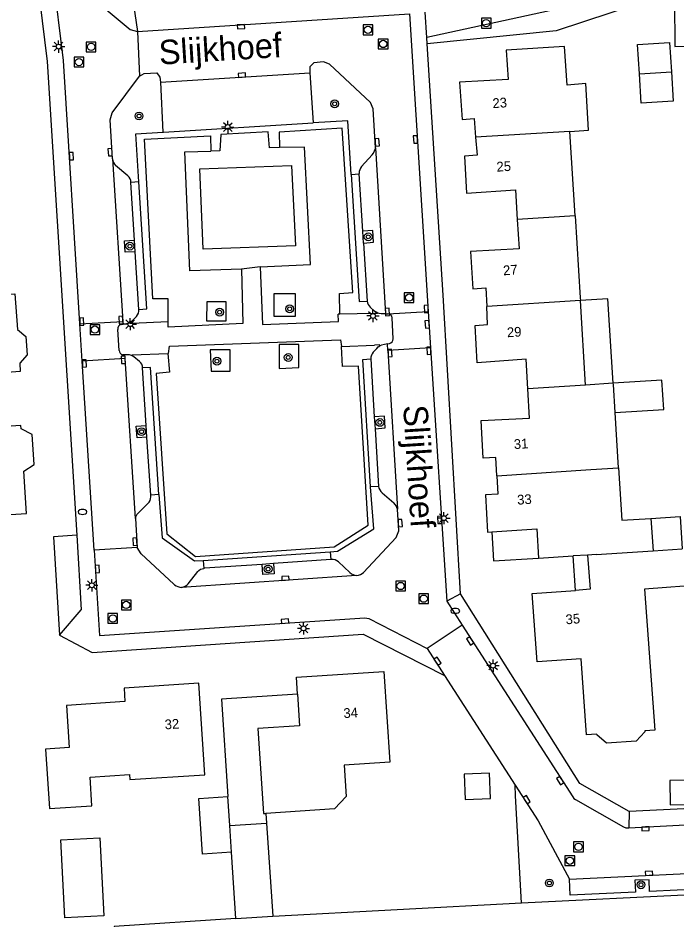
# Model space of a CAD drawing. Extents: x 140000 to 143000, y 403500 to 406000.
# Drawn here: x 140652.7 to 140720.3, y 403899.8 to 403992.2 of the extents above; entities that cross this region are included whole.
import ezdxf

# ---------------------------------------------------------------- set-up
doc = ezdxf.new("R2010")
doc.units = 0
for name, color, linetype in [('gg-afsc-erfafscheiding', 7, 'Continuous'), ('gg-afsc-hekwerk', 7, 'Continuous'), ('gg-anno-huisnummerreeks BGT', 7, 'Continuous'), ('gg-anno-openbare ruimte label', 7, 'Continuous'), ('gg-bbg-bassin', 7, 'Continuous'), ('gg-bbg-bijgebouw', 7, 'Continuous'), ('gg-bbg-gedigitaliseerde bebouwing', 7, 'Continuous'), ('gg-bbg-gedigitaliseerde bijgebouw', 7, 'Continuous'), ('gg-bbg-hoofdgebouw', 7, 'Continuous'), ('gg-bbg-luifel en loopbrug', 7, 'Continuous'), ('gg-bbg-overig bouwwerk', 7, 'Continuous'), ('gg-bbg-tussenscheiding', 7, 'Continuous'), ('gg-knt-bronhoudergrens', 7, 'Continuous'), ('gg-knt-verharding', 7, 'Continuous'), ('gg-knt-verharding nz', 7, 'Continuous'), ('gt-grn-groengrens', 7, 'Continuous'), ('gt-grn-weggrens', 7, 'Continuous'), ('gt-symb-boom', 7, 'Continuous'), ('gt-symb-brandkraan', 7, 'Continuous'), ('gt-symb-kolk', 7, 'Continuous'), ('gt-symb-lichtmast', 7, 'Continuous'), ('gt-symb-rioolschacht', 7, 'Continuous')]:
    doc.layers.add(name, color=color, linetype=linetype)

# ---------------------------------------------------------------- blocks, each defined once
blk = doc.blocks.new('gt0-BOOM')
at = {"layer": 'gt-symb-boom'}
for radius in [0.4, 0.2]:
    blk.add_circle((0, 0), radius, dxfattribs=at)
blk = doc.blocks.new('gt0-LMAST')
at = {"layer": 'gt-symb-lichtmast'}
for p, q in [((-0.182, 0.173), (-0.447, 0.438)), ((-0.005, 0.246), (-0.005, 0.621)), ((0.172, 0.173), (0.437, 0.438)), ((-0.255, -0.004), (-0.63, -0.004)), ((-0.182, -0.181), (-0.447, -0.446)), ((-0.005, -0.254), (-0.005, -0.629)), ((0.437, -0.446), (0.172, -0.181)), ((0.245, -0.004), (0.62, -0.004))]:
    blk.add_line(p, q, dxfattribs=at)
blk.add_circle((-0.005, -0.004), 0.25, dxfattribs=at)
blk = doc.blocks.new('gt0-KOLK')
at = {"layer": 'gt-symb-kolk'}
blk.add_lwpolyline([(0, 0), (0.375, 0), (0.375, 0.4), (-0.375, 0.4), (-0.375, 0), (0, 0)], dxfattribs=at)
blk = doc.blocks.new('gt0-RS')
at = {"layer": 'gt-symb-rioolschacht'}
blk.add_lwpolyline([(-0.5, -0.5), (0.5, -0.5), (0.5, 0.5), (-0.5, 0.5)], close=True, dxfattribs=at)
blk.add_circle((0, 0), 0.375, dxfattribs=at)
blk = doc.blocks.new('gt0-BR')
at = {"layer": 'gt-symb-brandkraan'}
for centre, radius, start, end in [((-0.244, 0), 0.206, 107.56694, 252.43307), ((0.599, -2.664), 3, 106.89205, 107.56694), ((0, -0.691), 0.938, 73.10799, 106.89205), ((-0.599, -2.664), 3, 72.43309, 73.10799), ((0.244, 0), 0.206, 287.56695, 72.43309), ((0.599, 2.664), 3, 252.43307, 253.10797), ((0, 0.691), 0.938, 253.10797, 286.89206), ((-0.599, 2.664), 3, 286.89206, 287.56695)]:
    blk.add_arc(centre, radius, start, end, dxfattribs=at)

msp = doc.modelspace()

# ---------------------------------------------------------------- linework, layer by layer
at = {"layer": 'gg-afsc-erfafscheiding'}
msp.add_lwpolyline([(140720.042, 403993.941), (140720.089, 403989.294), (140722.989, 403989.327)], dxfattribs=at)
at = {"layer": 'gg-afsc-hekwerk'}
msp.add_line((140704.351, 403901.52), (140759.387, 403904.142), dxfattribs=at)
at = {"layer": 'gg-bbg-bassin'}
msp.add_lwpolyline([(140661.095, 403908.172), (140661.513, 403900.183), (140657.519, 403899.973), (140657.101, 403907.962), (140661.095, 403908.172)], dxfattribs=at)
at = {"layer": 'gg-bbg-bijgebouw'}
for p, q in [((140674.425, 403909.422), (140678.194, 403909.672)), ((140674.605, 403906.711), (140674.425, 403909.422)), ((140678.194, 403909.672), (140678.828, 403900.136)), ((140675.058, 403899.886), (140674.605, 403906.711)), ((140675.058, 403899.886), (140678.828, 403900.136))]:
    msp.add_line(p, q, dxfattribs=at)
at = {"layer": 'gg-bbg-gedigitaliseerde bebouwing'}
for p, q in [((140717.637, 403940.917), (140717.843, 403937.605)), ((140717.843, 403937.605), (140720.836, 403937.797))]:
    msp.add_line(p, q, dxfattribs=at)
msp.add_lwpolyline([(140714.307, 403946.12), (140714.642, 403940.73), (140717.637, 403940.917)], dxfattribs=at)
at = {"layer": 'gg-bbg-gedigitaliseerde bijgebouw'}
msp.add_line((140716.445, 403986.508), (140719.738, 403986.713), dxfattribs=at)
msp.add_lwpolyline([(140719.738, 403986.713), (140719.925, 403983.719), (140716.631, 403983.513), (140716.445, 403986.508)], dxfattribs=at)
at = {"layer": 'gg-bbg-hoofdgebouw'}
for p, q in [((140709.856, 403971.943), (140709.318, 403980.609)), ((140710.935, 403954.593), (140710.396, 403963.268)), ((140713.77, 403954.777), (140710.935, 403954.593)), ((140714.307, 403946.12), (140713.955, 403951.783)), ((140706.092, 403936.853), (140709.64, 403937.069)), ((140711.137, 403937.16), (140709.64, 403937.069))]:
    msp.add_line(p, q, dxfattribs=at)
for points in [[(140709.318, 403980.609), (140711.236, 403980.738), (140710.939, 403985.498), (140709.023, 403985.356), (140708.777, 403989.304), (140702.794, 403988.932), (140702.983, 403985.936), (140697.998, 403985.634), (140698.263, 403981.816), (140699.506, 403981.939), (140699.65, 403980.024)], [(140699.65, 403980.024), (140699.79, 403978.15), (140698.489, 403978.074), (140698.727, 403974.283), (140703.722, 403974.6), (140703.915, 403971.576)], [(140703.915, 403971.576), (140704.107, 403968.557), (140699.108, 403968.283), (140699.352, 403964.463), (140700.682, 403964.574), (140700.782, 403962.649)], [(140709.856, 403971.943), (140710.38, 403963.521), (140710.396, 403963.268)], [(140641.292, 403953.188), (140641.151, 403955.124), (140640.368, 403955.07), (140639.541, 403955.761), (140639.228, 403960.249), (140638.818, 403960.22), (140638.382, 403966.463), (140640.871, 403966.675), (140645.859, 403967.02), (140646.101, 403963.519), (140652.387, 403963.949), (140652.639, 403960.296), (140653.49, 403959.574), (140653.632, 403957.695), (140652.879, 403956.832), (140652.938, 403955.972), (140646.138, 403955.477), (140646.282, 403953.504)], [(140705, 403954.218), (140704.826, 403957.242), (140699.803, 403956.862), (140699.59, 403960.714), (140700.879, 403960.797), (140700.782, 403962.649)], [(140713.955, 403951.783), (140713.776, 403954.656), (140713.77, 403954.777)], [(140701.829, 403945.289), (140701.734, 403947.175), (140700.419, 403947.089), (140700.202, 403950.954), (140705.173, 403951.198), (140705, 403954.218)], [(140637.097, 403947.294), (140637.221, 403945.317), (140642.701, 403945.662), (140643.011, 403940.763), (140653.582, 403941.439), (140653.297, 403945.755), (140654.369, 403946.457), (140654.168, 403949.537), (140653.01, 403950.099), (140652.988, 403950.436), (140646.512, 403950.011), (140646.282, 403953.504)], [(140701.829, 403945.289), (140701.923, 403943.417), (140700.65, 403943.327), (140700.881, 403939.513), (140701.308, 403939.541)], [(140701.308, 403939.541), (140705.91, 403939.844), (140706.092, 403936.853)], [(140723.032, 403937.938), (140723.313, 403934.132), (140716.98, 403933.664), (140718.047, 403919.203), (140716.999, 403919.131), (140717.005, 403919.051), (140716.127, 403918.09), (140713.064, 403917.885), (140712.066, 403918.72), (140712.062, 403918.79), (140711.024, 403918.718), (140710.484, 403926.533), (140705.967, 403926.221), (140705.445, 403933.211), (140709.902, 403933.544)], [(140711.137, 403937.16), (140711.398, 403933.656), (140709.902, 403933.544)], [(140681.383, 403922.899), (140681.27, 403924.641), (140690.243, 403925.215), (140690.837, 403915.934), (140686.166, 403915.635), (140686.372, 403912.412), (140685.169, 403911.138), (140678.128, 403910.67)], [(140664.182, 403914.16), (140671.863, 403914.646), (140671.264, 403924.022), (140663.583, 403923.531), (140663.672, 403922.135), (140657.687, 403921.752), (140657.95, 403917.426), (140655.532, 403917.273), (140655.917, 403911.177), (140660.289, 403911.453), (140660.103, 403914.403), (140664.151, 403914.659), (140664.182, 403914.16)], [(140681.383, 403922.899), (140681.592, 403919.66), (140677.305, 403919.375), (140677.885, 403910.654), (140678.128, 403910.67)]]:
    msp.add_lwpolyline(points, dxfattribs=at)
at = {"layer": 'gg-bbg-luifel en loopbrug'}
for p, q in [((140709.902, 403933.544), (140709.64, 403937.069)), ((140674.425, 403909.422), (140674.226, 403912.415)), ((140678.128, 403910.67), (140678.194, 403909.672))]:
    msp.add_line(p, q, dxfattribs=at)
for points in [[(140716.445, 403986.508), (140716.258, 403989.502), (140719.551, 403989.707), (140719.738, 403986.713)], [(140713.77, 403954.777), (140713.212, 403963.449), (140710.396, 403963.268)], [(140713.955, 403951.783), (140718.945, 403952.091), (140718.761, 403955.085), (140713.77, 403954.777)], [(140717.637, 403940.917), (140720.631, 403941.103), (140720.836, 403937.797)], [(140701.308, 403939.541), (140701.489, 403936.564), (140706.092, 403936.853)], [(140681.383, 403922.899), (140673.564, 403922.393), (140674.226, 403912.415)], [(140674.605, 403906.711), (140671.612, 403906.512), (140671.239, 403912.217), (140674.226, 403912.415)]]:
    msp.add_lwpolyline(points, dxfattribs=at)
at = {"layer": 'gg-bbg-overig bouwwerk'}
for points in [[(140701.07, 403914.804), (140698.472, 403914.699), (140698.577, 403912.101), (140701.175, 403912.206), (140701.07, 403914.804)], [(140723.557, 403914.133), (140719.558, 403914.055), (140719.607, 403911.555), (140723.606, 403911.634), (140723.557, 403914.133)]]:
    msp.add_lwpolyline(points, dxfattribs=at)
at = {"layer": 'gg-bbg-tussenscheiding'}
for p, q in [((140709.318, 403980.609), (140699.65, 403980.024)), ((140709.856, 403971.943), (140703.915, 403971.576)), ((140710.396, 403963.268), (140700.782, 403962.649)), ((140710.935, 403954.593), (140705, 403954.218)), ((140701.829, 403945.289), (140711.473, 403945.944)), ((140711.473, 403945.944), (140714.307, 403946.12)), ((140712.015, 403937.232), (140711.137, 403937.16)), ((140712.015, 403937.232), (140717.843, 403937.605))]:
    msp.add_line(p, q, dxfattribs=at)
at = {"layer": 'gg-knt-bronhoudergrens'}
msp.add_lwpolyline([(140675.058, 403899.886), (140662.57, 403899.066), (140665.057, 403874.512), (140671.301, 403809.584), (140674.353, 403776.444), (140676.609, 403755.474), (140681.92, 403701.97), (140682.207, 403697.656), (140682.745, 403694.004), (140682.865, 403689.705), (140681.271, 403683.857), (140676.531, 403669.406), (140671.096, 403652.846), (140666.701, 403639.081), (140663.411, 403627.696)], dxfattribs=at)
at = {"layer": 'gg-knt-verharding'}
for p, q in [((140719.854, 403995.738), (140694.645, 403990.221)), ((140664.947, 403990.851), (140692.847, 403992.657)), ((140692.847, 403992.657), (140694.794, 403962.129)), ((140694.645, 403990.221), (140694.481, 403992.826)), ((140694.685, 403989.591), (140694.645, 403990.221)), ((140682.648, 403986.613), (140682.973, 403981.479)), ((140667.312, 403985.635), (140667.554, 403980.526)), ((140667.626, 403980.53), (140682.973, 403981.479)), ((140667.554, 403980.526), (140667.626, 403980.53)), ((140662.398, 403977.774), (140662.397, 403977.79)), ((140687.949, 403977.008), (140689.047, 403978.202)), ((140663.973, 403976.05), (140662.718, 403977.101)), ((140686.894, 403976.185), (140687.707, 403976.235)), ((140687.707, 403976.235), (140687.704, 403976.283)), ((140688.068, 403970.363), (140687.707, 403976.235)), ((140665.109, 403975.431), (140664.289, 403975.359)), ((140664.664, 403969.455), (140664.289, 403975.359)), ((140688.152, 403969.149), (140688.068, 403970.363)), ((140664.725, 403968.25), (140664.664, 403969.455)), ((140688.152, 403969.149), (140688.517, 403963.203)), ((140665.099, 403962.35), (140664.725, 403968.25)), ((140677.538, 403966.703), (140675.646, 403966.491)), ((140689.278, 403961.919), (140685.714, 403961.868)), ((140688.84, 403962.597), (140689.274, 403962.188)), ((140690.626, 403961.899), (140694.794, 403962.129)), ((140694.794, 403962.129), (140695.032, 403958.409)), ((140659.058, 403960.869), (140663.462, 403961.097)), ((140663.462, 403961.097), (140663.479, 403960.834)), ((140668.092, 403961.061), (140664.364, 403960.91)), ((140685.714, 403961.868), (140685.539, 403961.866)), ((140690.401, 403961.901), (140690.626, 403961.899)), ((140691.189, 403959.345), (140691.082, 403961.488)), ((140659.298, 403957.055), (140659.058, 403960.869)), ((140663.074, 403958.147), (140662.943, 403960.299)), ((140663.288, 403960.799), (140663.479, 403960.834)), ((140685.893, 403958.55), (140689.286, 403958.686)), ((140690.601, 403958.827), (140690.807, 403958.871)), ((140690.642, 403958.144), (140690.601, 403958.827)), ((140695.032, 403958.409), (140690.642, 403958.144)), ((140695.032, 403958.409), (140696.688, 403932.44)), ((140663.703, 403957.307), (140659.298, 403957.055)), ((140663.678, 403957.698), (140663.447, 403957.705)), ((140663.703, 403957.307), (140663.678, 403957.698)), ((140664.025, 403957.687), (140663.678, 403957.698)), ((140664.422, 403957.687), (140668.07, 403957.831)), ((140664.429, 403957.592), (140664.422, 403957.687)), ((140668.07, 403957.831), (140668.137, 403957.834)), ((140689.147, 403957.962), (140689.312, 403958.146)), ((140660.518, 403937.672), (140659.298, 403957.055)), ((140665.845, 403950.437), (140665.49, 403956.36)), ((140688.889, 403957.276), (140689.246, 403951.348)), ((140689.246, 403951.348), (140689.354, 403950.121)), ((140665.925, 403949.244), (140665.845, 403950.437)), ((140689.354, 403950.121), (140689.693, 403944.204)), ((140666.318, 403943.309), (140665.925, 403949.244)), ((140689.693, 403944.204), (140688.862, 403944.161)), ((140690.047, 403943.559), (140691.273, 403942.503)), ((140664.991, 403941.42), (140666.15, 403942.603)), ((140667.135, 403943.385), (140666.318, 403943.309)), ((140664.748, 403940.924), (140664.937, 403937.95)), ((140658.721, 403939.199), (140659.197, 403931.549)), ((140671.703, 403936.613), (140684.738, 403937.51)), ((140684.738, 403937.51), (140684.794, 403936.701)), ((140671.703, 403936.613), (140671.771, 403935.803)), ((140678.916, 403936.295), (140677.742, 403936.209)), ((140684.794, 403936.701), (140678.916, 403936.295)), ((140684.852, 403936.705), (140684.794, 403936.701)), ((140686.747, 403935.366), (140685.564, 403936.479)), ((140668.765, 403934.123), (140668.697, 403934.186)), ((140696.688, 403932.44), (140698.266, 403929.99)), ((140656.966, 403928.941), (140659.197, 403931.549)), ((140694.661, 403927.597), (140696.443, 403924.828)), ((140696.443, 403924.828), (140703.688, 403913.572)), ((140715.366, 403909.208), (140755.823, 403911.204)), ((140678.828, 403900.136), (140704.351, 403901.52))]:
    msp.add_line(p, q, dxfattribs=at)
for points in [[(140615.699, 404080.633), (140615.983, 404080.638), (140635.008, 404078.847), (140638.477, 404076.282), (140642.369, 404054.461), (140650.122, 404032.814), (140655.697, 403987.762), (140658.721, 403939.199)], [(140659.058, 403960.869), (140657.359, 403987.877), (140654.173, 404013.729)], [(140660.746, 403995.983), (140660.968, 403994.124), (140661.338, 403993.459), (140664.224, 403991.043), (140664.947, 403990.851)], [(140720.042, 403993.941), (140717.377, 403993.874), (140716.911, 403993.862), (140716.325, 403993.67), (140707.904, 403990.905), (140694.685, 403989.591)], [(140698.108, 403933.172), (140696.304, 403963.806), (140694.685, 403989.591)], [(140689.386, 403978.908), (140689.143, 403982.916), (140688.86, 403983.56), (140684.642, 403987.479), (140684.053, 403987.73), (140683.036, 403987.639), (140682.626, 403987.223), (140682.648, 403986.613)], [(140662.397, 403977.79), (140662.142, 403981.796), (140662.376, 403982.493), (140665.166, 403986.256)], [(140665.166, 403986.256), (140665.661, 403986.533), (140666.945, 403986.614), (140667.267, 403986.174), (140667.312, 403985.635)], [(140679.525, 403978.948), (140678.505, 403978.926), (140678.372, 403980.55), (140673.495, 403980.286), (140673.392, 403978.618), (140672.492, 403978.59)], [(140675.646, 403966.491), (140670.325, 403966.31), (140669.833, 403978.509), (140672.492, 403978.59)], [(140677.538, 403966.703), (140682.721, 403966.945), (140682.1, 403979.003), (140679.525, 403978.948)], [(140680.745, 403977.112), (140681.17, 403968.872), (140671.686, 403968.536), (140671.354, 403976.779), (140680.745, 403977.112)], [(140686.894, 403976.185), (140687.69, 403963.154), (140688.517, 403963.203)], [(140665.099, 403962.35), (140665.919, 403962.42), (140665.109, 403975.431)], [(140688.152, 403969.149), (140689.172, 403969.235), (140689.106, 403970.438), (140688.068, 403970.363)], [(140664.725, 403968.25), (140663.697, 403968.209), (140663.622, 403969.383), (140664.664, 403969.455)], [(140677.538, 403966.703), (140677.776, 403960.806), (140685.569, 403961.121), (140685.539, 403961.866)], [(140675.646, 403966.491), (140675.77, 403960.895), (140668.114, 403960.519), (140668.092, 403961.061)], [(140689.578, 403961.99), (140689.417, 403962.076), (140689.274, 403962.188)], [(140689.578, 403961.99), (140689.583, 403961.923), (140689.278, 403961.919)], [(140690.401, 403961.901), (140689.949, 403961.909), (140689.76, 403961.932), (140689.578, 403961.99)], [(140663.479, 403960.834), (140664.019, 403960.934), (140664.195, 403961.004)], [(140664.86, 403961.632), (140664.355, 403961.109), (140664.195, 403961.004)], [(140664.364, 403960.91), (140664.202, 403960.899), (140664.195, 403961.004)], [(140668.137, 403957.834), (140668.243, 403958.585), (140685.798, 403959.225), (140685.893, 403958.55)], [(140689.807, 403958.613), (140689.801, 403958.714), (140689.286, 403958.686)], [(140689.312, 403958.146), (140689.503, 403958.359), (140689.643, 403958.5), (140689.807, 403958.613)], [(140690.601, 403958.827), (140689.979, 403958.688), (140689.807, 403958.613)], [(140665.162, 403957.022), (140664.598, 403957.497), (140664.429, 403957.592)], [(140667.135, 403943.385), (140666.31, 403956.397), (140665.49, 403956.36)], [(140688.862, 403944.161), (140688.072, 403957.203), (140688.889, 403957.276)], [(140689.354, 403950.121), (140690.37, 403950.21), (140690.29, 403951.405), (140689.246, 403951.348)], [(140665.925, 403949.244), (140664.911, 403949.192), (140664.835, 403950.368), (140665.845, 403950.437)], [(140688.155, 403935.389), (140691.503, 403938.959), (140691.762, 403939.649), (140691.628, 403941.859)], [(140658.721, 403939.199), (140656.337, 403939.02), (140656.966, 403928.941)], [(140668.697, 403934.186), (140665.339, 403937.284), (140664.937, 403937.95)], [(140660.518, 403937.672), (140661.069, 403928.915), (140688.273, 403930.734), (140688.688, 403930.656), (140694.661, 403927.597)], [(140677.742, 403936.209), (140671.832, 403935.82), (140671.771, 403935.803)], [(140678.916, 403936.295), (140678.976, 403935.248), (140677.814, 403935.172), (140677.742, 403936.209)], [(140670.152, 403934.213), (140671.154, 403935.488), (140671.254, 403935.59), (140671.439, 403935.713), (140671.771, 403935.803)], [(140715.406, 403910.882), (140710.35, 403913.742), (140698.108, 403933.172)], [(140698.266, 403929.99), (140709.612, 403912.375), (140709.735, 403912.2), (140709.902, 403912.085), (140714.812, 403909.287), (140715.063, 403909.208), (140715.366, 403909.208)], [(140656.966, 403928.941), (140660.301, 403927.183), (140688.112, 403929.056), (140696.443, 403924.828)], [(140758.57, 403916.178), (140755.461, 403912.836), (140715.406, 403910.882)], [(140704.351, 403901.52), (140703.751, 403912.484), (140703.688, 403913.572)], [(140703.688, 403913.572), (140706.048, 403909.906), (140709.275, 403903.941)], [(140725.994, 403903.077), (140717.493, 403902.674), (140717.441, 403903.881), (140715.981, 403903.825), (140716.038, 403902.605), (140709.347, 403902.308), (140709.275, 403903.941)]]:
    msp.add_lwpolyline(points, dxfattribs=at)
for centre, radius, start, end in [((140687.302, 403979.475), 2.16, 323.90657, 344.79559), ((140663.428, 403977.851), 1.033, 184.27991, 226.58067), ((140688.677, 403976.358), 0.976, 138.255, 184.40159), ((140663.359, 403975.352), 0.93, 0.45952, 48.69049), ((140689.463, 403963.318), 0.953, 186.95004, 229.16548), ((140664.082, 403962.29), 1.018, 319.78035, 3.39764), ((140690.638, 403961.454), 0.445, 4.33968, 91.60265), ((140663.368, 403960.375), 0.432, 100.67377, 190.11488), ((140690.726, 403959.328), 0.464, 280.11956, 2.14926), ((140663.503, 403958.131), 0.43, 177.85193, 262.46954), ((140663.984, 403956.608), 1.08, 65.68754, 87.84723), ((140689.849, 403957.307), 0.96, 136.95185, 181.82627), ((140664.531, 403956.297), 0.961, 3.76104, 48.95287), ((140690.653, 403944.311), 0.966, 186.37474, 231.1445), ((140665.441, 403943.145), 0.892, 322.6142, 10.61544), ((140690.079, 403941.425), 1.609, 15.65181, 42.07901), ((140665.495, 403940.866), 0.749, 132.26126, 175.53648), ((140684.929, 403935.712), 0.995, 50.35319, 94.42629), ((140687.458, 403936.117), 1.034, 226.56336, 269.18242), ((140687.399, 403936.167), 1.085, 272.32848, 314.18519), ((140669.397, 403934.817), 0.967, 274.96998, 321.32557), ((140669.508, 403935.012), 1.158, 230.12885, 268.68892)]:
    msp.add_arc(centre, radius, start, end, dxfattribs=at)
at = {"layer": 'gg-knt-verharding nz'}
for p, q in [((140667.312, 403985.635), (140682.648, 403986.613)), ((140689.386, 403978.908), (140690.401, 403961.901)), ((140662.398, 403977.774), (140663.462, 403961.097)), ((140664.748, 403940.924), (140663.703, 403957.307)), ((140690.642, 403958.144), (140691.628, 403941.859)), ((140687.443, 403935.083), (140669.481, 403933.854))]:
    msp.add_line(p, q, dxfattribs=at)
msp.add_lwpolyline([(140709.275, 403903.941), (140746.153, 403905.714), (140765.135, 403906.66), (140765.467, 403944.075)], dxfattribs=at)
at = {"layer": 'gt-grn-groengrens'}
for points in [[(140686.894, 403976.185), (140686.553, 403981.7), (140682.973, 403981.479)], [(140665.109, 403975.431), (140664.804, 403980.356), (140667.554, 403980.526)], [(140685.714, 403961.868), (140685.699, 403963.975), (140687.056, 403964.088), (140685.97, 403980.932), (140679.492, 403980.512), (140679.525, 403978.948)], [(140668.092, 403961.061), (140668.092, 403963.445), (140666.538, 403963.445), (140665.671, 403979.809), (140672.455, 403980.151), (140672.492, 403978.59)], [(140678.984, 403961.624), (140678.984, 403963.992), (140681.13, 403963.992), (140681.13, 403961.624), (140678.984, 403961.624)], [(140674.04, 403961.178), (140674.04, 403963.117), (140672.083, 403963.117), (140672.049, 403961.178), (140674.04, 403961.178)], [(140668.07, 403957.831), (140668.25, 403955.901), (140666.878, 403955.764), (140667.975, 403939.324), (140670.894, 403937.029), (140685.126, 403938.001), (140688.614, 403940.213), (140687.625, 403956.519), (140686, 403956.509), (140685.893, 403958.55)], [(140679.497, 403958.768), (140679.507, 403956.293), (140681.525, 403956.378), (140681.525, 403958.768), (140679.497, 403958.768)], [(140672.514, 403956.005), (140674.457, 403956.005), (140674.457, 403958.203), (140672.429, 403958.203), (140672.514, 403956.005)], [(140684.738, 403937.51), (140685.479, 403937.547), (140689.195, 403939.866), (140688.862, 403944.161)], [(140667.135, 403943.385), (140667.482, 403938.942), (140670.794, 403936.572), (140671.703, 403936.613)]]:
    msp.add_lwpolyline(points, dxfattribs=at)
at = {"layer": 'gt-grn-weggrens'}
for p, q in [((140664.553, 403993.598), (140664.947, 403990.851)), ((140664.947, 403990.851), (140665.166, 403986.256)), ((140664.937, 403937.95), (140660.518, 403937.672)), ((140698.108, 403933.172), (140696.688, 403932.44)), ((140698.266, 403929.99), (140694.661, 403927.597)), ((140715.406, 403910.882), (140715.366, 403909.208))]:
    msp.add_line(p, q, dxfattribs=at)

# ---------------------------------------------------------------- block references
at = {"layer": 'gt-symb-boom'}
for p in [(140685.183, 403983.43), (140665.121, 403982.185), (140688.629, 403969.793), (140664.181, 403968.832), (140673.384, 403962.068), (140680.571, 403962.409), (140673.11, 403957.043), (140680.419, 403957.425), (140689.822, 403950.763), (140665.378, 403949.815), (140678.359, 403935.729), (140707.215, 403903.539), (140716.608, 403903.358)]:
    msp.add_blockref('gt0-BOOM', p, dxfattribs=at)
at = {"layer": 'gt-symb-brandkraan'}
for p in [(140659.315, 403941.586), (140697.562, 403931.439)]:
    msp.add_blockref('gt0-BR', p, dxfattribs=at)
at = {"layer": 'gt-symb-kolk'}
for p, rotation in [((140675.563, 403991.538), -176.29328685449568), ((140675.682, 403986.169), 3.64982401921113), ((140689.351, 403979.473), -86.53592032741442), ((140693.668, 403979.787), 93.64982401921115), ((140662.353, 403978.483), 93.64982401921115), ((140657.977, 403978.048), -86.39849659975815), ((140690.39, 403962.08), -87.8206625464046), ((140694.777, 403962.402), 91.9371120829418), ((140659.045, 403961.089), -87.64294775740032), ((140663.452, 403961.276), 93.35887884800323), ((140694.876, 403960.843), 93.64982401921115), ((140690.658, 403957.858), -85.89713515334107), ((140695.05, 403958.125), 92.43767744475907), ((140663.712, 403957.187), 91.79999367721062), ((140659.314, 403956.806), -87.64294775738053), ((140691.715, 403940.429), -86.53592032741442), ((140696.156, 403940.784), 93.64982401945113), ((140664.899, 403938.55), 93.6578769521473), ((140660.641, 403935.724), -86.39849659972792), ((140680.152, 403934.584), 3.917145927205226), ((140680.109, 403930.188), 3.828031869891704), ((140699.245, 403928.471), 122.7880754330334), ((140695.573, 403926.18), -57.23664905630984), ((140708.475, 403914.14), 122.7880754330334), ((140704.716, 403911.975), -57.22986300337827), ((140717.068, 403909.292), -177.1742685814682), ((140717.445, 403904.334), 2.752795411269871)]:
    msp.add_blockref('gt0-KOLK', p, dxfattribs=dict(at, rotation=rotation))
at = {"layer": 'gt-symb-lichtmast'}
for p in [(140656.876, 403989.302), (140674.222, 403981.053), (140689.121, 403961.68), (140664.228, 403960.837), (140696.399, 403940.945), (140660.286, 403934.072), (140681.99, 403929.648), (140701.438, 403925.83)]:
    msp.add_blockref('gt0-LMAST', p, dxfattribs=at)
at = {"layer": 'gt-symb-rioolschacht'}
for p in [(140688.604, 403991.017), (140700.733, 403991.698), (140660.202, 403989.268), (140690.164, 403989.565), (140658.957, 403987.714), (140692.823, 403963.562), (140660.59, 403960.278), (140691.952, 403933.992), (140663.803, 403932.052), (140694.323, 403932.693), (140662.426, 403930.665), (140710.199, 403907.25), (140709.307, 403905.826)]:
    msp.add_blockref('gt0-RS', p, dxfattribs=at)

# ---------------------------------------------------------------- texts
at = {"layer": 'gg-anno-huisnummerreeks BGT'}
for s, rotation, p in [('23', 4, (140701.413, 403982.981)), ('25', 3.6, (140701.819, 403976.469)), ('27', 3.7, (140702.494, 403965.845)), ('29', 3.2, (140702.886, 403959.494)), ('31', 3.2, (140703.594, 403948.03)), ('33', 3.5, (140703.94, 403942.328)), ('35', 4.2, (140708.912, 403930.061)), ('34', 3.6, (140686.118, 403920.443)), ('32', 3.6, (140667.784, 403919.291))]:
    msp.add_text(s, height=1, rotation=rotation, dxfattribs=at).set_placement(p)
at = {"layer": 'gg-anno-openbare ruimte label'}
for rotation, p in [(3.6, (140667.226, 403987.44)), (273.6, (140692.212, 403952.489))]:
    msp.add_text('Slijkhoef', height=2.5, rotation=rotation, dxfattribs=at).set_placement(p)

doc.saveas('drawing.dxf')
